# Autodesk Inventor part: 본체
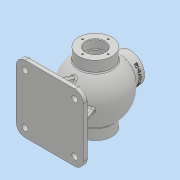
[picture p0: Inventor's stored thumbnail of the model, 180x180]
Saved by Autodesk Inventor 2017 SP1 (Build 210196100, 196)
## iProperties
Part Number: 본체
Material: 일반
Document SubType Name: Modeling
Designer: MRC
Density: 1 g/cm^3
Appearance: 기본값
Author: MRC
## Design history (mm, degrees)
sketch "스케치1"
  geometry: L1 (0, 65)-(0, -65); L2 (0, 65)-(31, 65); L3 (31, -65)-(0, -65); L4 (31, 65)-(31, 44.215); L5 (31, -44.215)-(31, -65); A1 r 54 centre (0, 0) between (31, -44.215) and (31, 44.215); A2 r 44 centre (0, 0) between (0, -44) and (0, 44); 2 further points
  constraints: 10 end point, 4 coincident, 4 perpendicular, 4 point on circle, 2 centre point, 2 point on line, 1 horizontal, 1 midpoint, 1 vertical
  dimensions: "d1" = 130 distance of L1.start L1.end; "d2" = 108 diameter of A1; "d4" = 62 diameter of L4 L1; "d5" = 62 diameter of L5 L1; "d6" = 88 diameter of A2
revolve "회전1" sketch "스케치1" stored, may be unused: angle "d7" = 90 deg
node "작업 평면1"
sketch "스케치2"
  geometry: C1 r 27 at (0, 0); 1 further point
  constraints: 1 centre point, 1 coincident
  dimensions: "d9" = 54 diameter of C1
extrude "돌출1" join sketch "스케치2" stored distance "d10" = 10; taper "d11" = 0 deg
sketch "스케치4"
  geometry: C1 r 31 at (0, 0) reference; C2 r 17.5 at (0, 0)
  constraints: 1 centre point, 1 coincident
  dimensions: "d12" = 35 diameter of C2
extrude "돌출2" cut sketch "스케치4" distance "d13" = 16; taper "d14" = 0 deg
sketch "스케치5"
  geometry: C1 r 17.5 at (0, 0) reference; C2 r 15 at (0, 0)
  constraints: 1 centre point, 1 coincident
  dimensions: "d15" = 30 diameter of C2
extrude "돌출3" cut sketch "스케치5" stored distance "d16" = 16; taper "d17" = 0 deg
sketch "스케치6"
  geometry: C1 r 31 at (0, 0) reference; C2 r 17.5 at (0, 0)
  constraints: 1 centre point, 1 coincident
  dimensions: "d18" = 35 diameter of C2
extrude "돌출4" cut sketch "스케치6" distance "d19" = 16; taper "d20" = 0 deg
sketch "스케치7"
  geometry: C1 r 17.5 at (0, 0) reference; C2 r 15 at (0, 0)
  constraints: 1 centre point, 1 coincident
  dimensions: "d21" = 30 diameter of C2
extrude "돌출5" cut sketch "스케치7" stored distance "d22" = 16; taper "d23" = 0 deg
sketch "스케치8"
  geometry: C1 r 27 at (0, 0) reference; C2 r 13 at (0, 0)
  constraints: 1 centre point, 1 coincident
  dimensions: "d24" = 26 diameter of C2
extrude "돌출6" cut sketch "스케치8" stored distance "d25" = 16; taper "d26" = 0 deg
sketch "스케치9"
  geometry: C1 r 17.5 at (0, 0) reference; 1 further point
  constraints: 1 vertical alignment
  dimensions: "d27" = 24 distance of point (0, 24) C1.centre
hole "구멍1" sketch "스케치9" at (0, 24) diameter "d28" = 3.242; stored, may be unused: countersink angle "d32" = 90 deg, drill point angle "d34" = 118 deg; dims "d29" = 12, "d30" = 4, "d31" = 2, "d33" = 15
sketch "스케치10"
  geometry: C1 r 13 at (0, 0) reference; 1 further point
  constraints: 1 vertical alignment
  dimensions: "d38" = 20 distance of C1.centre point (0, 20)
hole "구멍2" sketch "스케치10" at (0, 20) diameter "d39" = 3.242; stored, may be unused: countersink angle "d43" = 90 deg, drill point angle "d45" = 118 deg; dims "d40" = 9, "d41" = 4, "d42" = 2, "d44" = 11
node "작업 평면2"
sketch "스케치11"
  geometry: L1 (62.5, -62.5)-(-62.5, -62.5); L2 (-62.5, -62.5)-(-62.5, 62.5); L3 (-62.5, 62.5)-(62.5, 62.5); L4 (62.5, 62.5)-(62.5, -62.5); L5 (62.5, -62.5)-(-62.5, 62.5); L6 (-62.5, -62.5)-(62.5, 62.5); 1 further point
  constraints: 12 end point, 2 midpoint, 2 parallel, 1 horizontal, 1 perpendicular
  dimensions: "d50" = 125 distance of L1.start L1.end; "d51" = 125 distance of L1.end L2.end
extrude "돌출7" join sketch "스케치11" distance "d52" = 10; taper "d53" = 0 deg
fillet "모깎기1" dims "d54" = 16
sketch "스케치13"
  geometry: L1 (-39.345, -44.351)-(-50.5, -75); L2 (40.483, -47.479)-(50.5, -75); L3 (-27, 46.765)-(-27, 65) reference; L4 (-27, 65)-(-21.621, 65) reference; L5 (-21.621, 65)-(-21.621, 54) reference; L6 (-21.621, 54)-(-20, 53.026) reference; L7 (-20, 53.026)-(-18.379, 54) reference; L8 (-18.379, 54)-(-18.379, 65) reference; L9 (-18.379, 65)-(-13, 65) reference; L10 (-13, 65)-(-13, 42.036) reference; L11 (13, 42.036)-(13, 65) reference; L12 (13, 65)-(18.379, 65) reference; L13 (18.379, 65)-(18.379, 54) reference; L14 (18.379, 54)-(20, 53.026) reference; L15 (20, 53.026)-(21.621, 54) reference; L16 (21.621, 54)-(21.621, 65) reference; L17 (21.621, 65)-(27, 65) reference; L18 (27, 65)-(27, 46.765) reference; L19 (62.5, -75)-(62.5, -85) reference; L20 (62.5, -85)-(-62.5, -85) reference; L21 (-62.5, -85)-(-62.5, -75) reference; L22 (-62.5, -75)-(62.5, -75) reference; A1 r 54 centre (0, 0) between (-27, 46.765) and (27, 46.765) reference; A2 r 44 centre (0, 0) between (-13, 42.036) and (13, 42.036) reference; 1 further point
  constraints: 4 end point, 2 point on line
  dimensions: "d55" = 110 deg angle of L1 L22; "d56" = 110 deg angle of L22 L2; "d57" = 12 distance of L2.end L19.start; "d58" = 12 distance of L21.end L1.end
  node "절단 모서리 투영1"
feature "리브1" dims "d59" = 20, "d60" = 8, "d61" = 0, "d62" = 0, "d63" = 1, "d64" = 1
feature "리브2" dims "d65" = 20, "d66" = 8, "d67" = 0, "d68" = 0, "d69" = 1, "d70" = 1
sketch "스케치14"
  geometry: L1 (17.5, -65)-(17.5, -49) reference; L2 (17.5, -49)-(15, -49) reference; L3 (15, -49)-(15, -41.364) reference; L4 (42.036, -13)-(65, -13) reference; L5 (65, -13)-(65, -18.379) reference; L6 (65, -18.379)-(54, -18.379) reference; L7 (54, -18.379)-(53.026, -20) reference; L8 (53.026, -20)-(54, -21.621) reference; L9 (54, -21.621)-(65, -21.621) reference; L10 (65, -21.621)-(65, -27) reference; L11 (65, -27)-(46.765, -27) reference; L12 (31, -44.215)-(31, -65) reference; L13 (31, -65)-(25.621, -65) reference; L14 (25.621, -65)-(25.621, -50) reference; L15 (25.621, -50)-(24, -49.026) reference; L16 (24, -49.026)-(22.379, -50) reference; L17 (22.379, -50)-(22.379, -65) reference; L18 (22.379, -65)-(17.5, -65) reference; L19 (17.5, 49)-(17.5, 65) reference; L20 (17.5, 65)-(22.379, 65) reference; L21 (22.379, 65)-(22.379, 50) reference; L22 (22.379, 50)-(24, 49.026) reference; L23 (24, 49.026)-(25.621, 50) reference; L24 (25.621, 50)-(25.621, 65) reference; L25 (25.621, 65)-(31, 65) reference; L26 (31, 65)-(31, 44.215) reference; L27 (46.765, 27)-(65, 27) reference; L28 (65, 27)-(65, 21.621) reference; L29 (65, 21.621)-(54, 21.621) reference; L30 (54, 21.621)-(53.026, 20) reference; L31 (53.026, 20)-(54, 18.379) reference; L32 (54, 18.379)-(65, 18.379) reference; L33 (65, 18.379)-(65, 13) reference; L34 (65, 13)-(42.036, 13) reference; L35 (15, 41.364)-(15, 49) reference; L36 (15, 49)-(17.5, 49) reference; L37 (-17.5, 65)-(-17.5, 49) reference; L38 (-17.5, 49)-(-15, 49) reference; L39 (-15, 49)-(-15, 41.364) reference; L40 (-15, -41.364)-(-15, -49) reference; L41 (-15, -49)-(-17.5, -49) reference; L42 (-17.5, -49)-(-17.5, -65) reference; L43 (-17.5, -65)-(-22.379, -65) reference; L44 (-22.379, -65)-(-22.379, -50) reference; L45 (-22.379, -50)-(-24, -49.026) reference; L46 (-24, -49.026)-(-25.621, -50) reference; L47 (-25.621, -50)-(-25.621, -65) reference; L48 (-25.621, -65)-(-31, -65) reference; L49 (-31, -65)-(-31, -44.215) reference; L50 (-53.852, -4)-(-75, -4) reference; L51 (-75, -4)-(-75, -62.5) reference; L52 (-75, -62.5)-(-85, -62.5) reference; L53 (-85, -62.5)-(-85, 62.5) reference; L54 (-85, 62.5)-(-75, 62.5) reference; L55 (-75, 62.5)-(-75, 4) reference; L56 (-75, 4)-(-53.852, 4) reference; L57 (-31, 44.215)-(-31, 65) reference; L58 (-31, 65)-(-25.621, 65) reference; L59 (-25.621, 65)-(-25.621, 50) reference; L60 (-25.621, 50)-(-24, 49.026) reference; L61 (-24, 49.026)-(-22.379, 50) reference; L62 (-22.379, 50)-(-22.379, 65) reference; L63 (-22.379, 65)-(-17.5, 65) reference; L64 (-57.314, -44.063)-(-75, -50.5)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; A1 r 44 centre (0, 0) between (15, -41.364) and (42.036, -13) reference; A2 r 54 centre (0, 0) between (31, -44.215) and (46.765, -27) reference; A3 r 54 centre (0, 0) between (46.765, 27) and (31, 44.215) reference; A4 r 44 centre (0, 0) between (42.036, 13) and (15, 41.364) reference; A5 r 44 centre (0, 0) between (-15, 41.364) and (-15, -41.364) reference; A6 r 54 centre (0, 0) between (-53.852, -4) and (-31, -44.215) reference; A7 r 54 centre (0, 0) between (-31, 44.215) and (-53.852, 4) reference; 1 further point
  constraints: 4 end point, 2 point on line
  dimensions: "d71" = 110 deg angle of L51 L64; "d72" = 110 deg angle of L55 L65; "d73" = 12 distance of L65.end L54.end; "d74" = 12 distance of L51.end L64.end
  node "절단 모서리 투영2"
feature "리브3" dims "d75" = 20, "d76" = 8, "d77" = 0, "d78" = 0, "d79" = 1, "d80" = 1
feature "리브4" dims "d81" = 20, "d82" = 8, "d83" = 0, "d84" = 0, "d85" = 1, "d86" = 1
sketch "스케치15"
  geometry: C1 r 5.5 at (-46.5, 46.5); C2 r 5.5 at (46.5, 46.5); C3 r 5.5 at (46.5, -46.5); C4 r 5.5 at (-46.5, -46.5); A1 r 16 centre (-46.5, 46.5) between (-46.5, 62.5) and (-62.5, 46.5) reference; A2 r 16 centre (-46.5, -46.5) between (-62.5, -46.5) and (-46.5, -62.5) reference; A3 r 16 centre (46.5, -46.5) between (46.5, -62.5) and (62.5, -46.5) reference; A4 r 16 centre (46.5, 46.5) between (62.5, 46.5) and (46.5, 62.5) reference; 1 further point
  constraints: 4 centre point, 4 coincident
  dimensions: "d87" = 11 diameter of C1; "d88" = 11 diameter of C2; "d89" = 11 diameter of C3; "d90" = 11 diameter of C4
extrude "돌출8" cut sketch "스케치15" stored distance "d91" = 10; taper "d92" = 0 deg
fillet "모깎기2" dims "d93" = 3
fillet "모깎기3" dims "d94" = 3
fillet "모깎기4" dims "d95" = 3
fillet "모깎기5" dims "d96" = 3
chamfer "모따기1" distance "d97" = 1; stored, may be unused: second distance "d98" = 2, angle "d99" = 45 deg
fillet "모깎기6" dims "d100" = 0.6
fillet "모깎기7" dims "d101" = 0.6
fillet "모깎기8" dims "d102" = 3
fillet "모깎기9" dims "d103" = 3
node "작업 평면3"
sketch "스케치16"
  geometry: L1 (65, 27)-(65, -27) reference; 2 further points
  constraints: 1 horizontal alignment, 1 other
  dimensions: "d105" = 9 distance from line of L1 point (56, 0)
feature "엠보싱1" sketch "스케치16" dims "d1" = 130, "d2" = 108, "d4" = 62, "d5" = 62, "d6" = 88, "d12" = 35, "d106" = 0.5, "d107" = 0
node "솔리드1"
pattern_circular "원형 패턴1" dims angle "d36" = 360 deg
mirror "미러1"
pattern_circular "원형 패턴2" dims angle "d47" = 360 deg
other parameters: "d3" = 62, "d8" = 65, "d49" = -85, "d104" = 27
